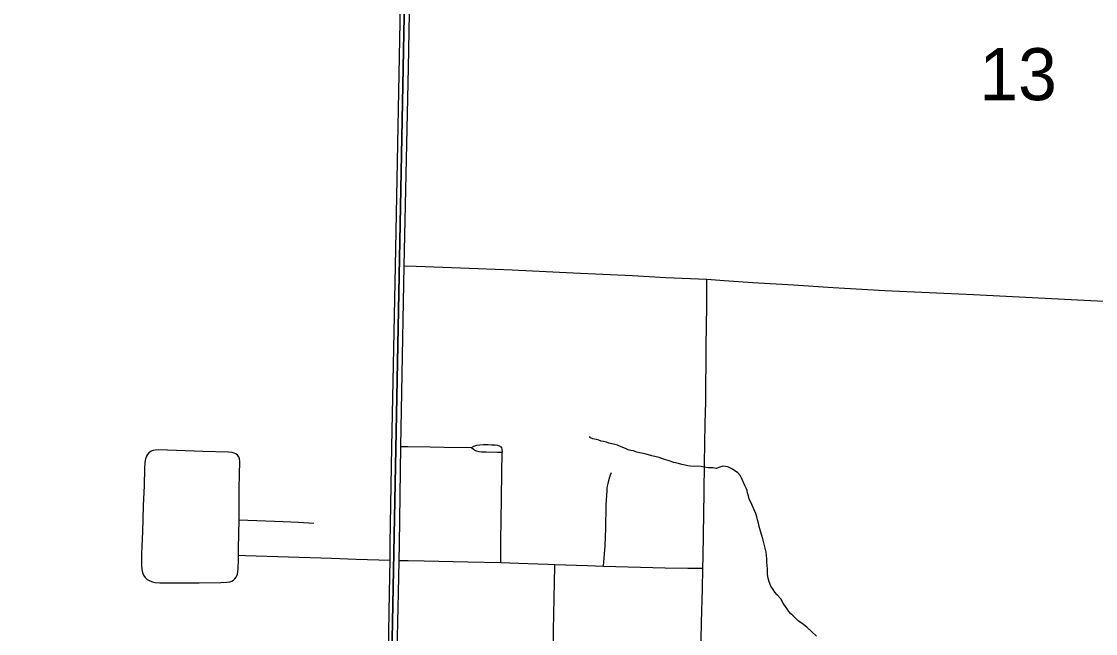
# Model space of a CAD drawing. Extents: x 0 to 34, y 0 to 22.
# Drawn here: x 6.168 to 7.032, y 19.449 to 19.941 of the extents above; entities that cross this region are included whole.
import ezdxf

# ---------------------------------------------------------------- set-up
doc = ezdxf.new("R2010")
doc.units = 0
for name, color, linetype in [('GM_X_City_Street', 7, 'Continuous'), ('GM_X_Minor_River', 7, 'Continuous'), ('GM_X_Section', 7, 'Continuous'), ('GM_X_Section_Text', 7, 'Continuous'), ('GM_X_State_Route', 7, 'Continuous')]:
    doc.layers.add(name, color=color, linetype=linetype)

msp = doc.modelspace()

# ---------------------------------------------------------------- linework, layer by layer
at = {"layer": 'GM_X_City_Street'}
for points in [[(6.476, 19.74462), (6.48566, 19.74426), (6.53546, 19.74239), (6.56276, 19.74133), (6.61183, 19.73903), (6.65965, 19.73671), (6.68633, 19.73522), (6.71916, 19.73373)], [(6.71443, 19.42842), (6.71508, 19.45799), (6.71571, 19.48472), (6.71603, 19.50125), (6.71622, 19.51083), (6.71708, 19.56243), (6.71737, 19.58544), (6.71786, 19.61776), (6.71836, 19.63518), (6.71875, 19.6799), (6.71928, 19.71225), (6.71918, 19.73135), (6.71916, 19.73373)], [(6.71916, 19.73373), (6.7333, 19.7328), (6.75625, 19.73119), (6.78905, 19.72916), (6.82082, 19.72711), (6.86241, 19.72477), (6.93383, 19.72142), (7.02261, 19.71681), (7.12381, 19.71173), (7.1741, 19.70916), (7.21944, 19.70705), (7.26289, 19.70489), (7.29829, 19.70305), (7.35354, 19.7003), (7.40445, 19.69765), (7.43984, 19.69601), (7.45406, 19.69497), (7.46561, 19.69412)], [(6.34327, 19.5401), (6.3433, 19.5654), (6.34341, 19.57661), (6.34374, 19.58713), (6.34346, 19.58941), (6.34286, 19.59095), (6.34192, 19.59222), (6.34069, 19.5932), (6.33923, 19.59388), (6.33758, 19.5943), (6.3346, 19.59458), (6.31406, 19.59511), (6.27867, 19.59658), (6.27569, 19.59639), (6.27402, 19.59602), (6.27245, 19.59535), (6.27064, 19.59406), (6.26956, 19.59283), (6.26869, 19.5914), (6.26789, 19.58925), (6.26736, 19.58634), (6.26711, 19.58144), (6.26677, 19.56773), (6.26595, 19.55161), (6.26549, 19.53047), (6.26481, 19.51309), (6.26473, 19.50381), (6.26499, 19.50019), (6.2655, 19.49791), (6.26639, 19.49579), (6.26768, 19.49392), (6.26933, 19.49235), (6.27129, 19.49114), (6.27344, 19.49029), (6.27575, 19.48978), (6.27936, 19.48945), (6.28988, 19.48944), (6.31102, 19.48959), (6.32845, 19.48991), (6.33335, 19.48996), (6.33565, 19.4903), (6.33723, 19.49085), (6.33861, 19.49177), (6.33965, 19.49287), (6.34084, 19.49404), (6.34182, 19.49651), (6.34248, 19.50045), (6.34263, 19.50856), (6.34269, 19.51174)], [(6.47312, 19.59924), (6.47874, 19.59917), (6.49682, 19.59896), (6.50819, 19.59868), (6.53007, 19.59841)], [(6.53007, 19.59841), (6.53189, 19.59949), (6.53431, 19.60033), (6.53678, 19.60064), (6.53962, 19.60082), (6.54337, 19.6007), (6.54617, 19.60062), (6.54922, 19.60053), (6.55101, 19.60032), (6.5516, 19.60008), (6.55246, 19.59972), (6.5531, 19.59926), (6.55359, 19.59883), (6.55407, 19.59805), (6.55438, 19.59708), (6.55462, 19.59473)], [(6.53007, 19.59841), (6.53177, 19.59695), (6.53316, 19.59598), (6.53415, 19.5957), (6.53595, 19.59526), (6.5382, 19.59503), (6.54195, 19.59483), (6.55091, 19.5947), (6.55462, 19.59473)], [(6.55356, 19.50595), (6.55356, 19.50731), (6.55361, 19.52415), (6.55397, 19.53903), (6.55455, 19.57751), (6.55462, 19.59473)], [(6.6362, 19.50298), (6.63747, 19.51955), (6.63813, 19.53334), (6.63847, 19.55205), (6.6391, 19.56386), (6.63928, 19.5656), (6.63945, 19.56736), (6.6399, 19.5694), (6.64045, 19.57187), (6.6414, 19.57479), (6.64195, 19.57647), (6.64273, 19.57828)], [(6.34269, 19.51174), (6.34279, 19.51704), (6.34327, 19.5401)], [(6.34327, 19.5401), (6.3786, 19.53886), (6.39098, 19.53831), (6.40336, 19.53765)], [(6.34269, 19.51174), (6.34828, 19.51155), (6.38299, 19.51041), (6.41759, 19.50927), (6.43745, 19.5086), (6.46457, 19.50783)], [(6.47203, 19.50762), (6.47914, 19.50748), (6.49195, 19.50723), (6.52712, 19.50636), (6.55356, 19.50595), (6.57542, 19.50506), (6.59157, 19.50454), (6.59711, 19.50433), (6.62321, 19.50335), (6.6362, 19.50298), (6.68588, 19.50155), (6.7039, 19.50134), (6.71292, 19.50127), (6.71603, 19.50125)], [(6.59565, 19.43122), (6.59568, 19.43243), (6.59603, 19.4514), (6.59709, 19.50295), (6.59711, 19.50433)]]:
    msp.add_lwpolyline(points, dxfattribs=at)
at = {"layer": 'GM_X_Minor_River'}
for points in [[(6.64754, 19.60017), (6.64414, 19.60103), (6.64037, 19.6019), (6.6385, 19.60271), (6.63623, 19.60316), (6.63435, 19.60359), (6.63247, 19.60441), (6.6302, 19.60485), (6.62756, 19.60531), (6.62568, 19.60612), (6.62531, 19.60651), (6.62534, 19.60727)], [(6.80753, 19.44655), (6.80347, 19.45047), (6.79978, 19.45399), (6.79606, 19.45676), (6.79307, 19.45875), (6.79048, 19.4611), (6.78864, 19.46306), (6.78679, 19.46463), (6.78533, 19.46657), (6.78386, 19.46852), (6.78241, 19.47084), (6.78058, 19.47317), (6.77878, 19.47665), (6.77584, 19.47977), (6.774, 19.48211), (6.77254, 19.48405), (6.77072, 19.48676), (6.7693, 19.49023), (6.76863, 19.49329), (6.76796, 19.49635), (6.76804, 19.499), (6.7681, 19.50091), (6.76779, 19.50357), (6.76749, 19.50624), (6.76757, 19.5089), (6.76727, 19.51157), (6.76696, 19.51424), (6.76424, 19.52496), (6.76356, 19.52764), (6.76252, 19.53109), (6.76181, 19.53302), (6.76149, 19.53493), (6.76081, 19.53761), (6.76013, 19.54029), (6.75943, 19.54259), (6.75875, 19.54527), (6.75732, 19.54835), (6.75662, 19.55027), (6.75447, 19.55489), (6.75339, 19.55683), (6.75271, 19.55951), (6.75202, 19.56181), (6.75169, 19.56372), (6.75099, 19.56564), (6.74992, 19.56795), (6.74885, 19.57026), (6.74777, 19.57257), (6.74634, 19.57565), (6.74413, 19.578), (6.74153, 19.57997), (6.73892, 19.58157), (6.73629, 19.58279), (6.73441, 19.58322), (6.73213, 19.58329), (6.72983, 19.58259), (6.72676, 19.58154), (6.72412, 19.582), (6.72032, 19.58211), (6.71692, 19.58259), (6.71465, 19.58303), (6.71239, 19.58348), (6.70934, 19.58318), (6.70592, 19.58328), (6.70404, 19.58372), (6.70177, 19.58416), (6.69912, 19.58462), (6.69649, 19.58545), (6.69272, 19.58632), (6.68896, 19.58757), (6.68519, 19.58882), (6.68106, 19.59046), (6.67502, 19.59177), (6.6705, 19.59305), (6.66673, 19.59391), (6.66296, 19.59478), (6.66032, 19.59562), (6.65805, 19.59606), (6.65617, 19.5965), (6.65392, 19.5977), (6.65054, 19.59894), (6.64754, 19.60017)]]:
    msp.add_lwpolyline(points, dxfattribs=at)
at = {"layer": 'GM_X_Section'}
for points in [[(5.48293, 20.43816), (6.48534, 20.43303), (6.46596, 19.43025), (5.4561, 19.43741)], [(6.48534, 20.43303), (7.47924, 20.38842), (7.45332, 19.38122), (6.71521, 19.42448), (6.46596, 19.43025)]]:
    msp.add_lwpolyline(points, close=True, dxfattribs=at)
at = {"layer": 'GM_X_State_Route'}
for points in [[(6.46479, 19.52084), (6.46612, 19.59885), (6.46901, 19.74424), (6.47355, 19.98326), (6.47621, 20.10924), (6.47654, 20.13859), (6.4767, 20.14839), (6.47702, 20.16435), (6.47767, 20.20037)], [(6.47935, 19.9038), (6.4806, 19.96287), (6.48103, 19.98348), (6.48105, 19.98448)], [(6.47218, 19.52057), (6.47312, 19.59924), (6.476, 19.74462), (6.47935, 19.9038)], [(6.46411, 19.48148), (6.46457, 19.50783), (6.46479, 19.52084)], [(6.4714, 19.48148), (6.47203, 19.50762), (6.47218, 19.52057)], [(6.46543, 19.30785), (6.46206, 19.31376), (6.46118, 19.32317), (6.46228, 19.37055), (6.46328, 19.43385), (6.46411, 19.48148)], [(6.46543, 19.30785), (6.46787, 19.31387), (6.46897, 19.32308), (6.47006, 19.37046), (6.47027, 19.43423), (6.4714, 19.48148)]]:
    msp.add_lwpolyline(points, dxfattribs=at)

# ---------------------------------------------------------------- texts
at = {"layer": 'GM_X_Section_Text'}
msp.add_text('13', height=0.041856, rotation=0.00001, dxfattribs=at).set_placement((6.93847, 19.8778))

doc.saveas('drawing.dxf')
